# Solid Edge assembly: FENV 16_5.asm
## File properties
Title: Zylinder
Author: bmolnar
Template: iso assembly.asm
Last saved by: bmolnar
Revision: 6
Application: Solid Edge
Username: bmolnar
Dokumentum tartalom típus: 1
Document Number: FENV 16/5
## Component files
Kolbenstange.par
Profilrohr.par
Kit_1.par
Kit_2.par
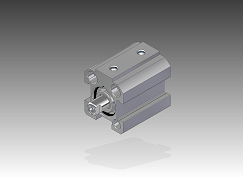
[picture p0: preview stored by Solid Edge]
